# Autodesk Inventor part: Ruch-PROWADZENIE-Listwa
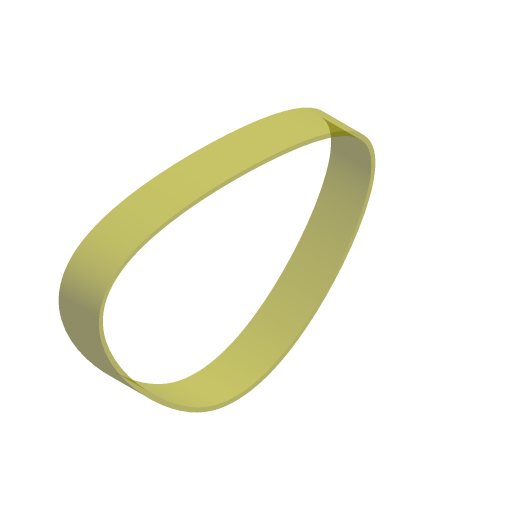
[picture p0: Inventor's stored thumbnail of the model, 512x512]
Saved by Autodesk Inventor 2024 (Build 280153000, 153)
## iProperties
Company: ATC
Created: 2023-03
Part Number: Ruch-PROWADZENIE-Listwa
Document SubType Name: Modeling
Designer: Andrzej Jaskulski
Manufacturer: Standard
Standards Organization: Custom
Material: Kurs-AJ
Stock Number: Ruch-PROWADZENIE-Listwa
Density: 1 g/cm^3
Appearance: Przezroczyste — żółte
Checked By: A.J.
Engr Approved By: Andrzej Jaskulski
Mfg Approved By: Andrzej Jaskulski
Authority: A.J.
Title: A.J.: Kurs R2024-MEP
Author: Andrzej Jaskulski
Revision Number: 1/24
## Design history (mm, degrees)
sketch "Sketch2" dims "d18" = 1.5
  geometry: 7 further points
  constraints: 2 horizontal alignment, 1 vertical alignment, 9 other
  dimensions: "d11" = 20 horizontal distance of point (30, -43.333) point (50, -50); "d12" = 20 horizontal distance of point (50, -50) point (70, -43.333) (= d11); "d13" = 50 horizontal distance of point (50, -50) point (0, 0); "d14" = 50 horizontal distance of point (50, -50) point (100, 0) (= d13); "d15" = 20 vertical distance of point (50, 20) point (0, 0) (= d11); "d16" = 50 horizontal distance of point (0, 0) point (50, -50) (= d13); "d17" = 6.66667 vertical distance of point (30, -43.333) point (50, -50) (= 0.333333 x d11)
extrude "Extrusion2" new body sketch "Sketch2" distance "d6" = 15; taper "d7" = 0 deg
node "Bryła1"
node "Korpusy bryłowe"
node "Korpusy powierzchniowe"
